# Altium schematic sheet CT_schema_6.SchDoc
size 144 x 123 mm
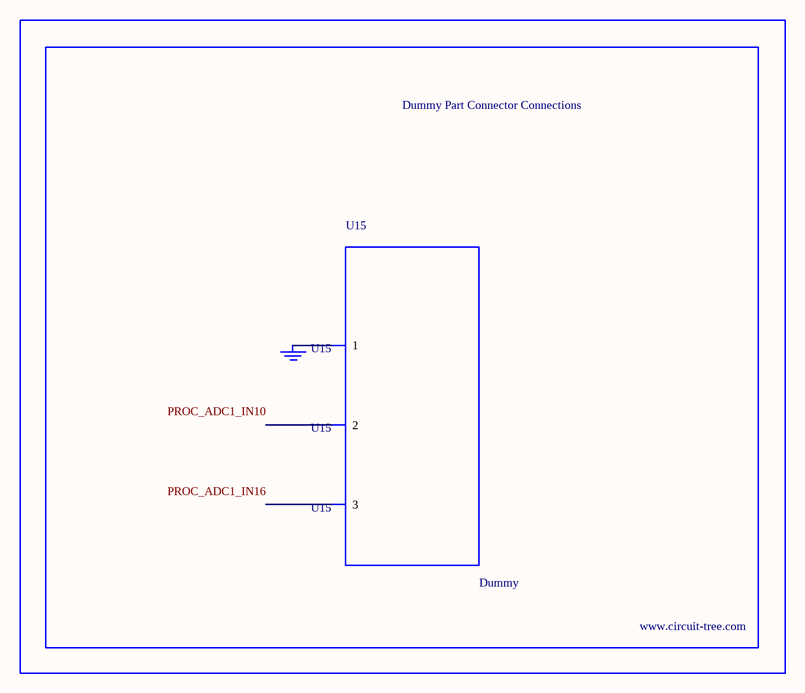
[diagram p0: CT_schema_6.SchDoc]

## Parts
BORDER5  (no value)
GND_INSTANCE_5_0  (no value)
U15  Dummy  [DUMMY_PACKAGE_129]

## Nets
NetGND_INSTANCE_5_0_0: GND_INSTANCE_5_0.0(GND) U15.1

Not connected (* = marked no-connect by the designer): U15 2 3

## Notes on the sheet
- Labels drawn without touching a wire or pin: PROC_ADC1_IN10, PROC_ADC1_IN16

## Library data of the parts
BORDER5 = BORDER_PAGE5
GND_INSTANCE_5_0 = GND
